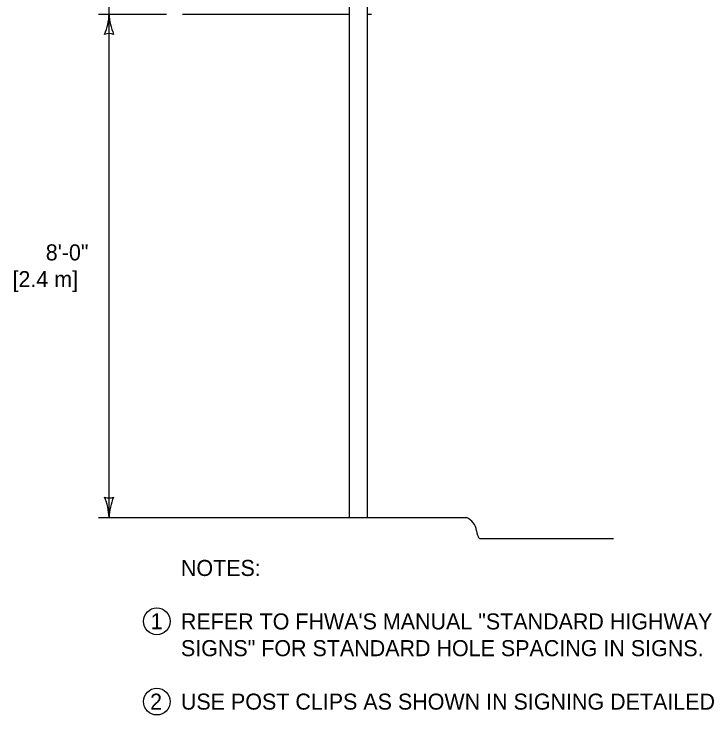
# Model space of a CAD drawing. Extents: x 49991.4 to 50021, y 49987.6 to 50011.4.
# Drawn here: x 50009.455 to 50012.072, y 49993.762 to 49996.384 of the extents above; entities that cross this region are included whole.
import ezdxf

# ---------------------------------------------------------------- set-up
doc = ezdxf.new("R2010")
doc.units = 0
for name, color, linetype in [('Level 1', 7, 'Continuous'), ('Level 2', 7, 'Continuous'), ('Level 3', 7, 'Continuous')]:
    doc.layers.add(name, color=color, linetype=linetype)

msp = doc.modelspace()

# ---------------------------------------------------------------- linework, layer by layer
at = {"layer": 'Level 1'}
for p, q in [((50010.7083, 49997.5059), (50010.7083, 49994.5009)), ((50010.7748, 49997.5059), (50010.7748, 49994.5009)), ((50010.0853, 49996.3843), (50010.7083, 49996.3843)), ((50010.7748, 49996.3843), (50010.7919, 49996.3843)), ((50009.7703, 49994.5009), (50011.147, 49994.5009)), ((50011.1965, 49994.4222), (50011.6965, 49994.4222))]:
    msp.add_line(p, q, dxfattribs=at)
for centre, start, end in [((50011.1233, 49994.4448), 5.9118, 67.1491), ((50011.2445, 49994.4574), 185.9118, 213.2855)]:
    msp.add_arc(centre, 0.061, start, end, dxfattribs=at)
msp.add_spline([(50011.1936, 49994.4239), (50011.1949, 49994.423), (50011.1965, 49994.4222)], degree=3, dxfattribs=at)
at = {"layer": 'Level 2'}
for centre in [(50009.9888, 49994.1125), (50009.9888, 49993.8121)]:
    msp.add_circle(centre, 0.05, dxfattribs=at)
at = {"layer": 'Level 3'}
for p, q in [((50009.8103, 49996.3843), (50009.8103, 49997.1918)), ((50009.7703, 49996.3843), (50010.0253, 49996.3843)), ((50009.8103, 49994.5009), (50009.8103, 49996.3843))]:
    msp.add_line(p, q, dxfattribs=at)
for centre, radius, start, end in [((50009.5882, 49996.3935), 0.2223, 337.456, 357.6395), ((50010.043, 49996.3958), 0.233, 182.8273, 202.0772), ((50009.8103, 49996.2561), 0.0548, 72.1388, 107.8612), ((50009.8103, 49994.6291), 0.0548, 252.1388, 287.8612), ((50009.5776, 49994.4894), 0.233, 2.8273, 22.0772), ((50009.8103, 49994.6291), 0.0548, 252.1388, 287.8612), ((50009.5776, 49994.4894), 0.233, 2.8273, 22.0772), ((50010.0324, 49994.4917), 0.2223, 157.456, 177.6395), ((50010.0324, 49994.4917), 0.2223, 157.456, 177.6395)]:
    msp.add_arc(centre, radius, start, end, dxfattribs=at)

# ---------------------------------------------------------------- texts
at = {"layer": 'Level 2'}
for s, p in [('8\'-0"', (50009.5734, 49995.4626)), ('[2.4 m]', (50009.4489, 49995.3626)), ('NOTES:', (50010.0788, 49994.2821)), ('1', (50009.9659, 49994.0829)), ('REFER TO FHWA\'S MANUAL "STANDARD HIGHWAY', (50010.0788, 49994.0821)), ('SIGNS" FOR STANDARD HOLE SPACING IN SIGNS.', (50010.0788, 49993.9821)), ('2', (50009.9636, 49993.7821)), ('USE POST CLIPS AS SHOWN IN SIGNING DETAILED', (50010.0788, 49993.7821))]:
    msp.add_text(s, height=0.06, dxfattribs=at).set_placement(p)

doc.saveas('drawing.dxf')
